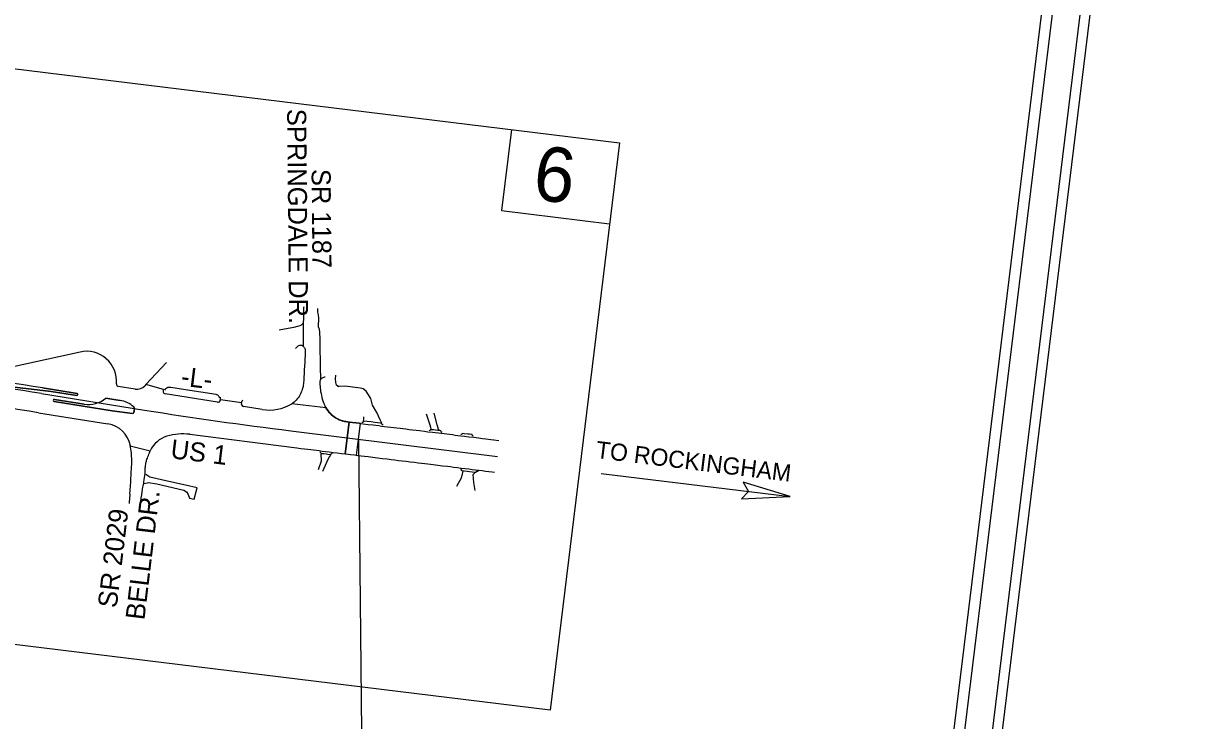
# Model space of a CAD drawing. Extents: x 1756435 to 1766932, y 416863 to 426859.
# Drawn here: x 1764409 to 1766576, y 423037 to 424317 of the extents above; entities that cross this region are included whole.
import ezdxf

# ---------------------------------------------------------------- set-up
doc = ezdxf.new("R2010")
doc.units = 0
for name, color, linetype in [('Exist Roads Curbs', 7, 'Continuous'), ('Exist Roads EOP', 7, 'Continuous'), ('Exist Roads EOP Other', 7, 'Continuous'), ('Exist Roads Soil', 7, 'Continuous'), ('Prop Horizontal Alignment', 7, 'Continuous'), ('Prop Horizontal Alignment Station Label', 7, 'Continuous'), ('Prop Shade Light', 7, 'Continuous'), ('Prop Shade Medium', 7, 'Continuous'), ('Prop Terminator CELL', 7, 'Continuous'), ('Sheet Data Field CELL', 7, 'Continuous'), ('Sheet Plan CELL', 7, 'Continuous'), ('Sheet Plot Border Inside CELL', 7, 'Continuous'), ('Sheet Plot Border Outside CELL', 7, 'Continuous'), ('Sheet Title CELL', 7, 'Continuous')]:
    doc.layers.add(name, color=color, linetype=linetype)

# ---------------------------------------------------------------- blocks, each defined once
blk = doc.blocks.new('Terminator')
at = {"layer": 'Prop Terminator CELL'}
blk.add_lwpolyline([(-9, 1.55), (0, 0), (-9.05, -1.6), (-7.9, 0)], close=True, dxfattribs=at)

msp = doc.modelspace()

# ---------------------------------------------------------------- linework, layer by layer
at = {"layer": 'Exist Roads Curbs'}
for p, q in [((1764669.4, 423645.2), (1764667.9, 423643.4)), ((1764706.6, 423644.2), (1764679.5, 423648.3)), ((1764763.2, 423635.2), (1764706.6, 423644.2)), ((1764769.2, 423629.2), (1764768.8, 423630.4))]:
    msp.add_line(p, q, dxfattribs=at)
for points in [[(1764679.5, 423648.3), (1764676.9, 423648.5), (1764674, 423648.1), (1764670.9, 423646.5), (1764669.4, 423645.2)], [(1764768.8, 423630.4), (1764767.9, 423632), (1764766.7, 423633.5), (1764765, 423634.6), (1764763.2, 423635.2)]]:
    msp.add_spline(points, degree=3, dxfattribs=at)
at = {"layer": 'Exist Roads EOP'}
for points in [[(1764923.8, 423796.2), (1764923.6, 423794.7), (1764923.5, 423791.2), (1764923.4, 423787), (1764923.4, 423783.1), (1764923.3, 423779.3), (1764923.3, 423775.8), (1764923.2, 423772.6), (1764923, 423769.6), (1764922.9, 423766.7), (1764922.7, 423763.7), (1764922.6, 423760.1), (1764922.5, 423752.3), (1764922.5, 423740.3), (1764922.5, 423724.1), (1764923.1, 423723.6), (1764923.9, 423722.9), (1764924.7, 423722.1), (1764925.4, 423721.2), (1764925.8, 423720.2), (1764926.1, 423719.1), (1764926.3, 423718.1), (1764926.4, 423717.1), (1764926.5, 423716), (1764926.5, 423714.9), (1764926.4, 423712.4), (1764926.1, 423707.2), (1764925.8, 423700.6), (1764925.5, 423694), (1764925.1, 423687.4), (1764924.8, 423680.7), (1764924.4, 423673.9), (1764924, 423667.1), (1764923.7, 423661.3), (1764923.4, 423657.5), (1764923.2, 423655), (1764922.9, 423652.7), (1764922.5, 423650.5), (1764922.1, 423648.4), (1764921.6, 423646.4), (1764921.1, 423644.4), (1764920.4, 423642.3), (1764919.3, 423639.7), (1764918.1, 423637), (1764916.7, 423634.4), (1764915.1, 423631.9), (1764913.5, 423629.5), (1764911.7, 423627.3), (1764910.1, 423625.3), (1764908.3, 423623.4), (1764906.3, 423621.6), (1764903.6, 423619.7), (1764901.8, 423618.6)], [(1764948.8, 423793.6), (1764949, 423789.7), (1764949.2, 423786.8), (1764949.5, 423784.4), (1764950, 423782.1), (1764950.4, 423779.8), (1764950.6, 423777.3), (1764950.7, 423774.3), (1764950.6, 423770), (1764950.4, 423765.9), (1764950.3, 423763.1), (1764950.3, 423761.3), (1764950.4, 423759.9), (1764950.6, 423758.9), (1764950.7, 423758.5), (1764950.8, 423758.3), (1764951.3, 423757.4), (1764952.3, 423755.6), (1764952.8, 423750.1), (1764953, 423745.5), (1764953.1, 423741.6), (1764953.2, 423737.9), (1764953.2, 423733.4), (1764953.3, 423726.7), (1764953.3, 423719.9), (1764953.5, 423714.7), (1764953.6, 423710.2), (1764953.7, 423705.3), (1764953.7, 423700), (1764953.8, 423694.4), (1764953.9, 423688.8), (1764954, 423683.4), (1764954.1, 423678), (1764954.3, 423672.4), (1764954.5, 423667.3), (1764954.6, 423663.3), (1764954.2, 423662.1), (1764953.8, 423661), (1764953.6, 423659.9), (1764953.5, 423658.6), (1764953.5, 423656.5), (1764953.6, 423653.4), (1764953.8, 423650), (1764954.1, 423647.1), (1764954.4, 423644.2), (1764954.8, 423641), (1764955.5, 423637.4), (1764956.4, 423633.6), (1764957.3, 423629.7), (1764958.3, 423625.8), (1764959.3, 423622.3), (1764960.4, 423619.2), (1764961.6, 423616.5), (1764962.8, 423614), (1764964.3, 423611.4), (1764966.3, 423608.3), (1764968.5, 423605.3), (1764970.7, 423602.7), (1764972.8, 423600.4), (1764974.9, 423598.3), (1764977.2, 423596.3), (1764979.8, 423594.4), (1764982.4, 423592.6), (1764984.8, 423591.2), (1764987, 423590.1), (1764989.1, 423589.2), (1764991, 423588.4), (1764992.6, 423587.9), (1764994.1, 423587.4), (1764995.6, 423586.9), (1764997.1, 423586.5), (1764998.9, 423586.1), (1765001.2, 423585.7), (1765004.1, 423585.2), (1765008, 423584.8), (1765013.2, 423584.1), (1765019.2, 423583.4), (1765025.7, 423582.6), (1765033, 423581.7), (1765041.8, 423580.7), (1765051.4, 423579.5), (1765056.3, 423578.9), (1765061.4, 423578.3), (1765066.6, 423577.6), (1765072, 423577), (1765077.6, 423576.3), (1765083.5, 423575.6), (1765089.3, 423574.9), (1765095, 423574.2), (1765100.6, 423573.5), (1765105.9, 423572.9), (1765111.4, 423572.2), (1765117.2, 423571.5), (1765123.4, 423570.7), (1765130, 423569.9), (1765136.3, 423569.1), (1765145.8, 423568), (1765151.9, 423567.2), (1765160.2, 423566.2), (1765165.4, 423565.6), (1765171, 423564.9), (1765176.4, 423564.3), (1765181.6, 423563.7), (1765186.7, 423563), (1765191.7, 423562.4), (1765196.7, 423561.8), (1765201.7, 423561.1), (1765206.8, 423560.5), (1765212.4, 423559.8), (1765219.1, 423559), (1765227, 423558), (1765236, 423556.9), (1765244.9, 423555.8), (1765252.3, 423554.9), (1765258.3, 423554.2), (1765267.3, 423553.1), (1765272.6, 423552.4), (1765282, 423551.3)], [(1764606.7, 423516.8), (1764608.1, 423516.8), (1764607.7, 423523.6), (1764607.3, 423528.1), (1764606.9, 423531.5), (1764606.4, 423535.1), (1764605.8, 423538.7), (1764605.3, 423541.5)], [(1764623.8, 423432.6), (1764624.7, 423439.5), (1764625.5, 423445.7), (1764626.3, 423451.4), (1764627.1, 423456.7), (1764627.8, 423461.4), (1764628.3, 423465.2), (1764628.8, 423467.6), (1764629.1, 423468.5), (1764629.3, 423469.6), (1764629.6, 423471), (1764629.9, 423472.9), (1764630.4, 423475.3), (1764630.9, 423478.7), (1764631.5, 423482.9), (1764632, 423486.8), (1764632.3, 423490.4), (1764632.5, 423493.2), (1764632.5, 423495.4), (1764632.5, 423497.4), (1764632.6, 423499.1), (1764632.8, 423500.9), (1764633, 423502.7), (1764633.3, 423505), (1764633.7, 423507.6), (1764634, 423509.8), (1764634.4, 423511.5), (1764634.9, 423513.1), (1764635.3, 423514.7), (1764635.9, 423516.6), (1764636.6, 423518.7), (1764637.5, 423521.1), (1764638.4, 423523.6), (1764639.3, 423526.1), (1764640.3, 423528.6), (1764641.9, 423532.3)], [(1764906.4, 423538.1), (1764910.8, 423537.5), (1764918.6, 423536.5), (1764925.2, 423535.7), (1764931.1, 423535), (1764936.7, 423534.3), (1764942, 423533.6), (1764947, 423533), (1764952.1, 423532.4), (1764957.8, 423531.7), (1764963.9, 423530.9), (1764970.5, 423530.1), (1764977.6, 423529.2), (1764985.1, 423528.3), (1764993, 423527.4), (1765001.3, 423526.4), (1765009.4, 423525.4), (1765016.8, 423524.5), (1765023.4, 423523.7), (1765029.3, 423523), (1765035.3, 423522.3), (1765042.4, 423521.4), (1765050.4, 423520.4), (1765059.4, 423519.3), (1765068.5, 423518.1), (1765076.9, 423517.1), (1765084.5, 423516.2), (1765091.3, 423515.3), (1765097.8, 423514.5), (1765104.7, 423513.7), (1765112, 423512.9), (1765119.5, 423512), (1765127, 423511.1), (1765133.9, 423510.2), (1765140.3, 423509.5), (1765146.2, 423508.8), (1765151.7, 423508.1), (1765161.5, 423506.9), (1765170.2, 423505.8), (1765178.7, 423504.8), (1765187.6, 423503.7), (1765193, 423503), (1765199.1, 423502.2), (1765206, 423501.3), (1765213.1, 423500.4), (1765220.1, 423499.5), (1765226.7, 423498.7), (1765233.1, 423497.9), (1765239.4, 423497.2), (1765245.6, 423496.4), (1765251.7, 423495.7), (1765257.8, 423494.9), (1765263.9, 423494.2), (1765269.9, 423493.4), (1765273.9, 423493)], [(1764603.9, 423435.5), (1764604.1, 423438.3), (1764604.5, 423444), (1764605.2, 423452), (1764604.6, 423453.1), (1764605.1, 423459.4), (1764605.8, 423468.8), (1764606.1, 423474.1), (1764606.3, 423478.4), (1764606.5, 423482.4), (1764606.6, 423486.3), (1764606.8, 423490.1), (1764607.1, 423494), (1764607.4, 423497.8), (1764607.6, 423502.1), (1764607.9, 423506.9), (1764608, 423513), (1764608.1, 423516.5)]]:
    msp.add_lwpolyline(points, dxfattribs=at)
at = {"layer": 'Exist Roads EOP Other'}
for p, q in [((1764908.9, 423759.3), (1764878.7, 423753.6)), ((1764920.4, 423725.4), (1764918.5, 423725.2)), ((1764922.3, 423724.1), (1764920.4, 423725.4)), ((1764633.8, 423653.7), (1764671.5, 423694.4))]:
    msp.add_line(p, q, dxfattribs=at)
for points in [[(1764922.8, 423768.3), (1764922, 423766.2), (1764921, 423764.8), (1764919.2, 423763.1), (1764916.4, 423761.4), (1764912.6, 423760.2), (1764907.5, 423759)], [(1764963.2, 423667.3), (1764961.6, 423667.1), (1764959.8, 423666.7), (1764956.3, 423664.9), (1764955, 423663.5)], [(1765067.4, 423582.9), (1765064.3, 423589.1), (1765058.1, 423602.4), (1765050.2, 423615.7), (1765046.9, 423628.2), (1765038.4, 423641.7), (1765033, 423645.8), (1765028.2, 423647), (1765013.6, 423649.1), (1764999.6, 423650.8), (1764988.1, 423650.1), (1764987.2, 423649.5), (1764986.7, 423649.9), (1764983.5, 423653.3)], [(1764770.9, 423625.7), (1764771.1, 423627.7), (1764771.1, 423630.8), (1764771.1, 423630.9)], [(1764809.4, 423620), (1764809.6, 423620.7), (1764810.8, 423623.6), (1764811.8, 423625.1)], [(1765069.5, 423579.3), (1765068.8, 423579.7), (1765068, 423580.5), (1765067.4, 423581.6), (1765067, 423582.7), (1765064.2, 423583), (1765059.1, 423583.6), (1765054.1, 423584.1), (1765047.3, 423585), (1765040.4, 423585.9), (1765033.7, 423586.7), (1765033.3, 423585.5), (1765032.9, 423584.9), (1765032.2, 423584.5), (1765031.4, 423584.2), (1765030.5, 423584)], [(1765033.8, 423587.5), (1765034.1, 423590.4), (1765034.4, 423594.2)], [(1765154.3, 423568.9), (1765155, 423569.1), (1765155.8, 423569.7), (1765156.5, 423570.5), (1765156.8, 423571.2), (1765156.9, 423571.6), (1765157.5, 423571.5), (1765162, 423571), (1765165.9, 423570.5), (1765169.9, 423570), (1765172.8, 423569.7), (1765174.7, 423569.4), (1765175, 423569.2), (1765175.4, 423568.1), (1765175.8, 423567.4), (1765176.2, 423566.9), (1765177.1, 423566.2)], [(1765235, 423559.1), (1765234.1, 423559.6), (1765233.6, 423560.1), (1765233.2, 423560.6), (1765233, 423561.3), (1765232.8, 423562), (1765228.2, 423562.5), (1765225, 423562.8), (1765218.4, 423563.4), (1765214.7, 423563.6), (1765214.5, 423563.3), (1765213.9, 423562.6), (1765213.4, 423562.2), (1765212.7, 423562), (1765212, 423561.9)], [(1764951, 423497.5), (1764956.5, 423513.6), (1764955.6, 423526.7)], [(1764976.4, 423527.3), (1764975.4, 423527.2), (1764974.6, 423526.7), (1764974, 423526.2), (1764972.6, 423524.9), (1764968.3, 423525.4), (1764965.1, 423525.8), (1764960.7, 423526.3), (1764958.2, 423526.5), (1764956.2, 423526.7), (1764955.5, 423527.4), (1764955.2, 423528.4), (1764954.7, 423529.2), (1764954.1, 423529.8), (1764953.2, 423530.3)], [(1764972.9, 423524), (1764970.8, 423521.5), (1764966.3, 423512.5), (1764965.7, 423510.5), (1764958, 423494.1)], [(1765244.7, 423494.7), (1765243.8, 423494.5), (1765243, 423494.2), (1765242.2, 423493.8), (1765239.4, 423492.5), (1765237.7, 423492.5), (1765232.8, 423493), (1765227.9, 423493.6), (1765224.2, 423494.1), (1765219.3, 423494.8), (1765214.6, 423495.6), (1765213.7, 423496), (1765213.5, 423496.6), (1765213.2, 423497.5), (1765212.5, 423498.1), (1765211.8, 423498.6)], [(1764630.9, 423472.3), (1764638.5, 423474.1), (1764653.8, 423471.2), (1764703.6, 423460.1), (1764708.3, 423456.5), (1764711.8, 423451.8), (1764714.1, 423445.3), (1764722.7, 423443), (1764727.9, 423464.1), (1764706.9, 423468.9), (1764676.2, 423475.6), (1764640.9, 423483.4), (1764633.6, 423488.7)]]:
    msp.add_lwpolyline(points, dxfattribs=at)
msp.add_spline([(1764918.5, 423725.2), (1764916, 423725.2), (1764913, 423724), (1764910.8, 423722.4), (1764908.7, 423720.1)], degree=3, dxfattribs=at)
at = {"layer": 'Exist Roads Soil'}
for points in [[(1764983.3, 423653.7), (1764982.4, 423663.9), (1764982.5, 423671)], [(1765148.6, 423600.3), (1765155.3, 423580.1), (1765156.4, 423575.6), (1765157, 423571.8)], [(1765172, 423570.1), (1765170.4, 423573.8), (1765168.8, 423579.9), (1765163.4, 423601.1)], [(1765215.8, 423494.9), (1765213, 423481.9), (1765204.2, 423466.8)], [(1765238.8, 423459.5), (1765236.3, 423473.9), (1765235, 423488.8), (1765238.1, 423491.8)]]:
    msp.add_lwpolyline(points, dxfattribs=at)
at = {"layer": 'Prop Horizontal Alignment'}
for p, q in [((1764442.4, 423637.1), (1764631.3, 423606.9)), ((1764900, 423568.8), (1765279.7, 423521.8))]:
    msp.add_line(p, q, dxfattribs=at)
for centre, start, end in [((1763235.6, 416093.6), 80.91031, 83.0234), ((1765838.1, 431150.4), 260.91031, 262.94578)]:
    msp.add_arc(centre, 7639.4, start, end, dxfattribs=at)
at = {"layer": 'Prop Horizontal Alignment Station Label'}
msp.add_lwpolyline([(1765024.5, 423553.3), (1765030.5, 422956.3), (1765872.2, 422853.3)], dxfattribs=at)
at = {"layer": 'Prop Shade Light'}
for p, q in [((1764513, 423713.5), (1764376.3, 423683.3)), ((1764460.1, 423641.1), (1764307, 423659)), ((1764614.1, 423645.5), (1764583, 423650.5)), ((1764633.8, 423653.7), (1764631.9, 423651.7)), ((1764666.4, 423644.7), (1764633.8, 423653.7)), ((1764444.1, 423647.7), (1764507.4, 423637.6)), ((1764560.4, 423628.8), (1764575.2, 423626.5)), ((1764765.2, 423621.2), (1764669.5, 423636.6)), ((1764571.9, 423605.5), (1764465.2, 423622.5)), ((1764465.9, 423626.5), (1764520.4, 423617.8)), ((1764609.6, 423600.7), (1764571.9, 423605.5)), ((1764575.2, 423626.5), (1764586.5, 423624.7)), ((1764612.9, 423609), (1764611.8, 423602.6)), ((1764809.4, 423620), (1764770.9, 423625.7)), ((1764847.5, 423608), (1764813.3, 423613.5)), ((1764964.5, 423611.2), (1764901.8, 423618.6)), ((1764436.8, 423602), (1764564.1, 423581.7)), ((1764611.8, 423602.6), (1764611.8, 423602.3)), ((1765007.3, 423584.8), (1765000, 423526.5)), ((1765000, 423526.5), (1765007.3, 423584.8)), ((1765025.7, 423582.6), (1765019.2, 423583.4)), ((1764714.4, 423562.5), (1764906.4, 423538.1)), ((1765028.1, 423582.3), (1765025.7, 423582.6)), ((1764605.3, 423541.5), (1764641.9, 423532.3)), ((1765000, 423526.5), (1765001.3, 423526.4)), ((1765016.8, 423524.5), (1765020.9, 423524))]:
    msp.add_line(p, q, dxfattribs=at)
for points in [[(1764506.8, 423633.6), (1764460.1, 423641.1), (1764460.1, 423641.1)], [(1765007.3, 423584.8), (1765004.1, 423585.2), (1765001.2, 423585.7), (1764998.9, 423586.1), (1764997.1, 423586.5), (1764995.6, 423586.9), (1764994.1, 423587.4), (1764992.6, 423587.9), (1764991, 423588.4), (1764989.1, 423589.2), (1764987, 423590.1), (1764984.8, 423591.2), (1764982.4, 423592.6), (1764979.8, 423594.4), (1764977.2, 423596.3), (1764974.9, 423598.3), (1764972.8, 423600.4), (1764970.7, 423602.7), (1764968.5, 423605.3), (1764966.3, 423608.3), (1764964.5, 423611.2)], [(1765019.2, 423583.4), (1765013.2, 423584.1), (1765008, 423584.8), (1765007.3, 423584.8)], [(1765020.9, 423524), (1765024.5, 423553.3), (1765028.1, 423582.3)], [(1764906.4, 423538.1), (1764910.8, 423537.5), (1764918.6, 423536.5), (1764925.2, 423535.7), (1764931.1, 423535), (1764936.7, 423534.3), (1764942, 423533.6), (1764947, 423533), (1764952.1, 423532.4), (1764957.8, 423531.7), (1764963.9, 423530.9), (1764970.5, 423530.1), (1764977.6, 423529.2), (1764985.1, 423528.3), (1764993, 423527.4), (1765000, 423526.5)], [(1765001.3, 423526.4), (1765009.4, 423525.4), (1765016.8, 423524.5)]]:
    msp.add_lwpolyline(points, dxfattribs=at)
for centre, radius, start, end in [((1764524.9, 423659.8), 55, 354.7941, 102.4915), ((1763235.6, 416093.6), 7650.2, 80.91031, 83.0234), ((1764583.6, 423654.5), 4, 174.7941, 260.8547), ((1764617.3, 423665.3), 20, 260.8547, 317.1532), ((1763235.6, 416093.6), 7603.9, 80.91031, 83.0234), ((1764507.1, 423635.6), 2, 260.9103, 80.9103), ((1764528.3, 423667.1), 50, 260.9103, 309.9907), ((1764670.3, 423641.6), 5, 140.8448, 260.8547), ((1764465.6, 423624.5), 2, 80.9103, 260.9103), ((1764578.7, 423576.3), 49, 47.7813, 80.8561), ((1764608.9, 423609.6), 4, 350.9103, 47.7813), ((1764766, 423626.1), 5, 260.8547, 354.752), ((1764814.1, 423618.4), 5, 161.243, 260.8547), ((1764860.2, 423686.9), 80, 260.8547, 301.2779), ((1764609.8, 423602.6), 2, 262.7097, 350.9103), ((1764609.9, 423602.9), 2, 350.9046, 350.9103), ((1764556.2, 423532.3), 50, 10.5575, 80.9103), ((1764701.8, 423463.2), 100, 82.7643, 106.9801), ((1764687.2, 423511.1), 50, 106.9801, 154.9356)]:
    msp.add_arc(centre, radius, start, end, dxfattribs=at)
at = {"layer": 'Prop Shade Medium'}
for p, q in [((1764307, 423659), (1764460.1, 423641.1)), ((1764507.4, 423637.6), (1764444.1, 423647.7)), ((1764460.1, 423641.1), (1764506.8, 423633.6)), ((1764575.2, 423626.5), (1764560.4, 423628.8)), ((1764465.2, 423622.5), (1764571.9, 423605.5)), ((1764520.4, 423617.8), (1764465.9, 423626.5)), ((1764571.9, 423605.5), (1764609.6, 423600.7)), ((1764586.5, 423624.7), (1764575.2, 423626.5)), ((1764611.8, 423602.3), (1764612.9, 423609))]:
    msp.add_line(p, q, dxfattribs=at)
for centre, radius, start, end in [((1763235.6, 416093.6), 7650.2, 80.91031, 83.0234), ((1764507.1, 423635.6), 2, 260.9103, 80.9103), ((1764528.3, 423667.1), 50, 260.9103, 309.9907), ((1764465.6, 423624.5), 2, 80.9103, 260.9103), ((1764578.7, 423576.3), 49, 47.7813, 80.8561), ((1764608.9, 423609.6), 4, 350.9103, 47.7813), ((1764609.8, 423602.6), 2, 262.7097, 350.9103)]:
    msp.add_arc(centre, radius, start, end, dxfattribs=at)
at = {"layer": 'Sheet Plan CELL'}
for p, q in [((1765305.1, 424122.2), (1765286.9, 423973.2)), ((1765286.9, 423973.2), (1765485.5, 423948.9)), ((1765469.8, 423490.5), (1765817.1, 423448))]:
    msp.add_line(p, q, dxfattribs=at)
msp.add_lwpolyline([(1764139.1, 424264.8), (1765503.7, 424097.9), (1765376.2, 423055.6), (1764011.6, 423222.6)], dxfattribs=at)
at = {"layer": 'Sheet Plot Border Inside CELL'}
msp.add_lwpolyline([(1759349.9, 422533.3), (1766029.4, 421715.9), (1766546.9, 425944.9), (1759867.4, 426762.2)], close=True, dxfattribs=at)
at = {"layer": 'Sheet Plot Border Outside CELL'}
msp.add_lwpolyline([(1766576, 426032.6), (1759826.3, 426858.6), (1759286.8, 422449.7), (1766036.5, 421623.8)], close=True, dxfattribs=at)
at = {"layer": 'Sheet Title CELL'}
for points in [[(1765985.5, 421772.4), (1766490.7, 425900.7)], [(1766058.6, 422536.3), (1766468.2, 425883.2)]]:
    msp.add_lwpolyline(points, dxfattribs=at)

# ---------------------------------------------------------------- block references
at = {"layer": 'Sheet Plan CELL', "xscale": 9.789102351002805, "yscale": -9.789102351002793, "rotation": -6.9766014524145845}
msp.add_blockref('Terminator', (1765817.1, 423448), dxfattribs=at)

# ---------------------------------------------------------------- texts
at = {"layer": 'Sheet Data Field CELL'}
for s, rotation, p in [('SPRINGDALE DR.', 270.5562, (1764893.2, 424160)), ('SR 1187', 270.5562, (1764938.1, 424049.6)), ('-L-', 353.0234, (1764697, 423652)), ('US 1', 353.0234, (1764677.9, 423518.6)), ('BELLE DR.', 83.1733, (1764631.1, 423220.3)), ('SR 2029', 83.1733, (1764580.2, 423242.3))]:
    msp.add_text(s, height=35, rotation=rotation, dxfattribs=at).set_placement(p)
at = {"layer": 'Sheet Plan CELL'}
for s, height, p in [('6', 100, (1765341.9, 423994.4)), ('TO ROCKINGHAM', 31.5, (1765459.1, 423519))]:
    msp.add_text(s, height=height, rotation=353.0234, dxfattribs=at).set_placement(p)

doc.saveas('drawing.dxf')
